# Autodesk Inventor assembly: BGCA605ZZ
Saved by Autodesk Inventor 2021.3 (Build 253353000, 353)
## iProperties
Created: 2021-10
Part Number: BGCA605ZZ
Document SubType Name: Assembly
Designer: Administrator
Title: BGCA605ZZ v2
Author: Administrator
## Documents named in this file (4)
- c:\worker\convert-fusion-r07\tmp\job-1\38\output\files\9d8713c4-8b5f-4a02-8819-57c3bb3edac1\00d5b2fc-d512-4b97-88e5-271aca2047e6.iam
- c:\worker\convert-fusion-r07\tmp\job-1\38\output\files\9d8713c4-8b5f-4a02-8819-57c3bb3edac1\_BGCA605ZZ_h.ipt
- c:\worker\convert-fusion-r07\tmp\job-1\38\output\files\9d8713c4-8b5f-4a02-8819-57c3bb3edac1\_bearing_605.ipt
- c:\worker\convert-fusion-r07\tmp\job-1\38\output\files\9d8713c4-8b5f-4a02-8819-57c3bb3edac1\_RRING-C-INT-S-14.ipt
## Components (3 placed, 3 different names)
1. _BGCA605ZZ_h:1
2. _bearing_605:1
3. _RRING-C-INT-S-14:1
